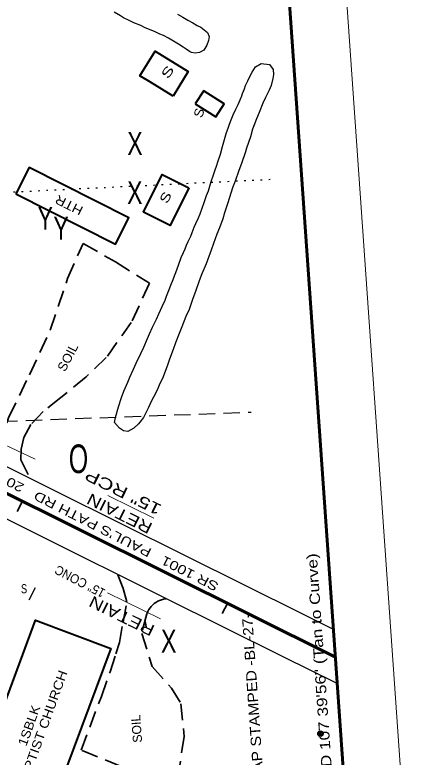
# Model space of a CAD drawing. Extents: x 2399800 to 2400616, y 567347 to 568869.
# Drawn here: x 2400344.6 to 2400525, y 568183.3 to 568507.5 of the extents above; entities that cross this region are included whole.
import ezdxf
from ezdxf.enums import TextEntityAlignment as Align

# ---------------------------------------------------------------- set-up
doc = ezdxf.new("R2010")
doc.units = 0
doc.header["$LTSCALE"] = 2.4
for name, pattern in [('DOTTED', [1.5, 0.3, -1.2]), ('LONG_DASHED', [7.5, 6, -1.5]), ('MEDIUM_DASHED', [4.5, 3, -1.5])]:
    doc.linetypes.add(name, pattern=pattern)
for name, color, linetype, lineweight in [('1', 7, 'Continuous', 40), ('11', 7, 'Continuous', 25), ('17', 7, 'MEDIUM_DASHED', 25), ('26', 7, 'LONG_DASHED', 35), ('3', 7, 'MEDIUM_DASHED', 35), ('38', 7, 'Continuous', 13), ('4', 7, 'Continuous', 35), ('6', 7, 'Continuous', 13), ('62', 7, 'Continuous', 60), ('63', 7, 'Continuous', 35), ('8', 7, 'Continuous', 40)]:
    doc.layers.add(name, color=color, linetype=linetype, lineweight=lineweight)
for name, color, linetype in [('23', 7, 'Continuous'), ('28', 7, 'Continuous'), ('5', 7, 'Continuous'), ('9', 7, 'Continuous')]:
    doc.layers.add(name, color=color, linetype=linetype)

msp = doc.modelspace()

# ---------------------------------------------------------------- linework, layer by layer
at = {"layer": '1'}
msp.add_line((2399965.144, 568485.991), (2400484.477, 568226.976), dxfattribs=at)
at = {"layer": '11', "linetype": 'DOTTED'}
msp.add_line((2400293.6, 568427.731), (2400455.985, 568435.717), dxfattribs=at)
at = {"layer": '11'}
for points in [[(2400415.538, 568507.84), (2400417.946, 568506.458), (2400420.064, 568505.191), (2400422.267, 568503.988), (2400424.18, 568502.9), (2400425.748, 568502.086), (2400427.287, 568501.047), (2400428.657, 568499.877), (2400429.339, 568498.113), (2400429.113, 568496.391), (2400428.39, 568494.354), (2400427.027, 568492.096), (2400425.224, 568491.115), (2400423.359, 568490.826), (2400421.722, 568491.117), (2400420.863, 568491.534), (2400419.314, 568492.498), (2400418.055, 568493.348), (2400415.957, 568494.765), (2400414.548, 568495.635), (2400413.064, 568496.515), (2400411.581, 568497.395), (2400409.444, 568498.512), (2400407.93, 568499.167), (2400405.773, 568500.135), (2400404.12, 568500.885), (2400401.439, 568501.922), (2400399.581, 568502.85), (2400396.546, 568504.086), (2400394.538, 568505.034), (2400392.036, 568506.275), (2400390.692, 568507.061), (2400387.93, 568508.641)], [(2400441.732, 568467.747), (2400442.046, 568468.429), (2400442.92, 568470.446), (2400443.595, 568472.109), (2400443.956, 568473.128), (2400444.755, 568475.155), (2400445.251, 568476.613), (2400446.294, 568478.76), (2400447.023, 568480.263), (2400448.151, 568482.476), (2400449.607, 568484.873), (2400452.153, 568486.291), (2400455.746, 568485.82), (2400457.372, 568483.704), (2400457.536, 568481.474), (2400457.152, 568479.697), (2400456.46, 568476.743), (2400455.576, 568474.65), (2400454.012, 568471.429), (2400452.855, 568468.992), (2400451.183, 568464.948), (2400450.127, 568462.117), (2400448.809, 568458.659)], [(2400388.052, 568329.476), (2400388.561, 568331.617), (2400389.862, 568336.319), (2400391.16, 568340.413), (2400392.206, 568343.169), (2400393.859, 568347.064), (2400394.837, 568349.296), (2400396.44, 568352.816), (2400397.541, 568355.413), (2400399.533, 568359.568), (2400400.814, 568362.369), (2400402.446, 568366.114), (2400403.414, 568368.272), (2400404.695, 568371.073), (2400405.549, 568372.941), (2400406.373, 568374.584), (2400407.436, 568376.881), (2400408.11, 568378.544), (2400408.86, 568380.196), (2400410.121, 568382.848), (2400410.825, 568384.736), (2400411.966, 568387.632), (2400412.661, 568389.444), (2400413.752, 568391.966), (2400414.333, 568393.488), (2400414.828, 568394.946), (2400416.018, 568398.216), (2400417.218, 568401.561), (2400418.196, 568403.794), (2400418.936, 568405.372), (2400419.516, 568406.894), (2400420.255, 568408.472), (2400421.338, 568410.919), (2400421.918, 568412.442), (2400422.905, 568414.749), (2400423.57, 568416.337), (2400424.672, 568418.933), (2400425.431, 568420.661), (2400426.488, 568423.492), (2400427.212, 568425.529), (2400428.222, 568428.594), (2400429.106, 568430.687), (2400430.254, 568434.799), (2400431.32, 568437.705), (2400431.93, 568439.453), (2400432.702, 568441.864), (2400433.123, 568443.331), (2400434.333, 568446.751), (2400435.288, 568449.976), (2400436.084, 568453.146), (2400436.936, 568456.156), (2400437.64, 568458.043), (2400438.334, 568459.856), (2400438.963, 568461.753), (2400439.846, 568463.845), (2400441.088, 568466.347), (2400442.046, 568468.429), (2400442.92, 568470.446), (2400443.595, 568472.109), (2400443.646, 568472.253)], [(2400454.291, 568472.003), (2400454.012, 568471.429), (2400452.855, 568468.992), (2400451.183, 568464.948), (2400450.127, 568462.117), (2400448.386, 568457.548), (2400447.421, 568454.248), (2400445.716, 568449.371), (2400445.275, 568447.753), (2400443.466, 568442.661), (2400442.37, 568439.531), (2400440.704, 568434.953), (2400439.638, 568432.047), (2400438.246, 568427.814), (2400437.349, 568425.038), (2400436.146, 568421.084), (2400435.419, 568418.439), (2400433.906, 568414.449), (2400432.794, 568411.778), (2400431.337, 568407.629), (2400430.271, 568404.723), (2400428.635, 568400.37), (2400428.054, 568398.847), (2400426.174, 568394.373), (2400425.023, 568391.402), (2400423.497, 568386.729), (2400422.326, 568383.609), (2400420.641, 568378.881), (2400419.246, 568375.79)], [(2400419.246, 568375.79), (2400417.441, 568371.306), (2400416.3, 568368.41), (2400414.767, 568364.271), (2400413.701, 568361.365), (2400412.084, 568357.161), (2400411.197, 568354.461), (2400409.248, 568349.463), (2400407.635, 568345.867), (2400406.657, 568343.635), (2400405.112, 568340.564), (2400404.034, 568338.726), (2400402.848, 568336.064), (2400402.118, 568334.561), (2400400.668, 568331.629), (2400399.121, 568329.7), (2400398.479, 568328.87), (2400396.483, 568327), (2400393.937, 568325.583), (2400392.075, 568325.903), (2400390.322, 568327.047), (2400388.052, 568329.476)]]:
    msp.add_lwpolyline(points, dxfattribs=at)
at = {"layer": '17'}
msp.add_line((2400252.161, 568326.829), (2400447.665, 568334.013), dxfattribs=at)
at = {"layer": '3', "linetype": 'Continuous', "lineweight": 25}
for points in [[(2400483.629, 568239.104), (2400470.246, 568245.798), (2400419.343, 568271.108), (2400362.072, 568299.673), (2400308.009, 568326.642), (2400253.449, 568353.932), (2400194.927, 568382.951), (2400136.831, 568411.76), (2400076.265, 568441.964), (2400023.623, 568468.434), (2399965.535, 568497.344), (2399964.308, 568497.949)], [(2400485.284, 568215.439), (2400462, 568226.988), (2400409.841, 568252.853), (2400354.423, 568280.585), (2400297.876, 568308.829), (2400245.542, 568334.846), (2400186.098, 568364.488), (2400128.133, 568393.345), (2400067.555, 568423.559), (2400013.737, 568450.439), (2399965.96, 568474.329)]]:
    msp.add_lwpolyline(points, dxfattribs=at)
at = {"layer": '3'}
for points in [[(2400332.041, 568314.84), (2400334.345, 568314.995), (2400337.329, 568319.172), (2400341.851, 568331.598), (2400350.923, 568350.281), (2400360.038, 568369.872), (2400367.626, 568392.327), (2400374.356, 568407.662), (2400388.532, 568399.637), (2400403.299, 568390.317), (2400395.415, 568373.154), (2400384.499, 568357.834), (2400375.714, 568349.468), (2400364.629, 568340.414), (2400356.97, 568334.261), (2400351.516, 568328.657), (2400348.55, 568322.878), (2400347.284, 568317.867), (2400347.21, 568313.233), (2400351.163, 568305.115)], [(2400390.638, 568179.356), (2400373.461, 568186.39), (2400382.339, 568209.818), (2400386.117, 568220.533), (2400388.621, 568228.398), (2400390.306, 568233.356), (2400391.791, 568242.348), (2400393.496, 568251.236), (2400391.886, 568256.983), (2400389.586, 568262.989)], [(2400410.59, 568252.482), (2400410.339, 568252.461), (2400409.458, 568252.307), (2400408.595, 568252.076), (2400407.754, 568251.768), (2400406.945, 568251.387), (2400406.173, 568250.934), (2400405.445, 568250.414), (2400404.765, 568249.832), (2400404.139, 568249.191), (2400403.573, 568248.497), (2400403.071, 568247.755), (2400402.637, 568246.971), (2400402.274, 568246.151), (2400402.165, 568245.858), (2400399.967, 568237.339), (2400404.532, 568222.983), (2400412.918, 568213.4), (2400417.102, 568206.645), (2400418.507, 568192.289), (2400416.388, 568178.75)]]:
    msp.add_lwpolyline(points, dxfattribs=at)
at = {"layer": '38'}
msp.add_line((2399965.144, 568485.991), (2400484.477, 568226.976), dxfattribs=at)
at = {"layer": '4'}
for p, q in [((2400347.878, 568295.105), (2400345.646, 568290.63)), ((2400437.366, 568250.473), (2400435.134, 568245.999))]:
    msp.add_line(p, q, dxfattribs=at)
at = {"layer": '6'}
for p, q in [((2400353.395, 568313.493), (2400330.494, 568324.157)), ((2400405.196, 568287.654), (2400385.211, 568297.575)), ((2400408.15, 568243.739), (2400385.02, 568255.047))]:
    msp.add_line(p, q, dxfattribs=at)
at = {"layer": '62'}
msp.add_line((2399965.144, 568485.991), (2400484.477, 568226.976), dxfattribs=at)
at = {"layer": '63', "lineweight": 13}
msp.add_line((2400524.992, 568005.982), (2400465.699, 568853.912), dxfattribs=at)
at = {"layer": '63', "lineweight": 60}
msp.add_line((2400442.155, 568832.216), (2400498.188, 568030.909), dxfattribs=at)
at = {"layer": '63', "lineweight": 53}
msp.add_circle((2400477.991, 568193.597), 0.919, dxfattribs=at)
at = {"layer": '8'}
for p, q in [((2400413.639, 568472.059), (2400403.731, 568478.144)), ((2400416.103, 568476.071), (2400413.639, 568472.059)), ((2400426.927, 568474.258), (2400423.334, 568468.598))]:
    msp.add_line(p, q, dxfattribs=at)
at = {"layer": '8', "lineweight": 25}
msp.add_line((2400350.865, 568251.97), (2400353.557, 568257.404), dxfattribs=at)
at = {"layer": '8'}
for points in [[(2400403.731, 568478.144), (2400399.172, 568480.944), (2400405.757, 568491.666), (2400420.224, 568482.781), (2400416.103, 568476.071)], [(2400427.164, 568474.218), (2400426.977, 568474.336), (2400426.927, 568474.258)], [(2400423.334, 568468.598), (2400432.272, 568462.923), (2400435.915, 568468.662), (2400427.164, 568474.218)]]:
    msp.add_lwpolyline(points, dxfattribs=at)
for points in [[(2400345.073, 568429.43), (2400388.565, 568407.382), (2400394.357, 568418.807), (2400350.865, 568440.855)], [(2400420.552, 568431.929), (2400412.352, 568415.532), (2400400.737, 568421.34), (2400408.937, 568437.738)], [(2400377.037, 568144.88), (2400313.925, 568168.365), (2400323.96, 568195.332), (2400334.338, 568191.47), (2400353.556, 568243.115), (2400386.515, 568230.85), (2400367.304, 568179.225), (2400387.079, 568171.866)]]:
    msp.add_lwpolyline(points, close=True, dxfattribs=at)

# ---------------------------------------------------------------- texts
at = {"layer": '11', "width": 0.75}
for s, p in [('X', (2400397.001, 568446.346)), ('X', (2400396.929, 568424.885)), ('Y', (2400357.844, 568413.638)), ('Y', (2400364.748, 568409.383)), ('X', (2400411.742, 568229))]:
    msp.add_text(s, height=10, dxfattribs=at).set_placement(p, align=Align.CENTER)
at = {"layer": '23'}
for s, rotation, width, p in [('SOIL', 62.305, 1.05, (2400369.445, 568357.044)), ("SR 1001   PAUL'S PATH RD   20' BST", 153.046, 1.3, (2400380.551, 568286.305))]:
    msp.add_text(s, height=4, rotation=rotation, dxfattribs=dict(at, width=width)).set_placement(p, align=Align.CENTER)
msp.add_text('SOIL', height=4, rotation=94.208, dxfattribs=at).set_placement((2400399.708, 568195.877), align=Align.CENTER)
at = {"layer": '26', "width": 0.95}
msp.add_text('15" CONC', height=4, rotation=152.417, dxfattribs=at).set_placement((2400373.92, 568261.815), align=Align.CENTER)
at = {"layer": '28'}
for s, rotation, width, p in [('S', 56.294, 1.5, (2400412.904, 568481.431)), ('S', 72.111, 1.1, (2400426.873, 568464.134)), ('HTR', 153.449, 1.15, (2400369.098, 568426.233)), ('S', 61.914, 1.35, (2400412.114, 568426.824)), ('BAPTIST CHURCH', 70.222, 1.15, (2400358.494, 568194.936)), ('1SBLK', 70.222, 1.1, (2400352.672, 568196.478))]:
    msp.add_text(s, height=4, rotation=rotation, dxfattribs=dict(at, width=width)).set_placement(p, align=Align.CENTER)
at = {"layer": '28', "width": 0.75}
for p in [(2400348.58, 568254.889), (2400348.596, 568254.889)]:
    msp.add_text('S', height=4, dxfattribs=at).set_placement(p, align=Align.CENTER)
at = {"layer": '5'}
for s, rotation, width, p in [('15" RCP', 153.597, 1.4, (2400409.129, 568293.193)), ('RETAIN', 153.597, 1.25, (2400405.127, 568285.132)), ('RETAIN', 153.945, 1.25, (2400406.114, 568240.482))]:
    msp.add_text(s, height=5, rotation=rotation, dxfattribs=dict(at, width=width)).set_placement(p)
at = {"layer": '63'}
for s, width, p in [('SKEW ANGLE FOR BENTS 111 02\'25" AND 107 39\'56" (Tan to Curve)', 1.25, (2400493, 568034.493)), ('NCDOT TRAVERSE STATION REBAR AND CAP STAMPED -BL-27-', 1.15, (2400463.073, 568032.4))]:
    msp.add_text(s, height=4.5, rotation=94, dxfattribs=dict(at, width=width)).set_placement(p)
at = {"layer": '9', "width": 0.65}
msp.add_text('O', height=12.5, dxfattribs=at).set_placement((2400372.348, 568307.39), align=Align.CENTER)

doc.saveas('drawing.dxf')
